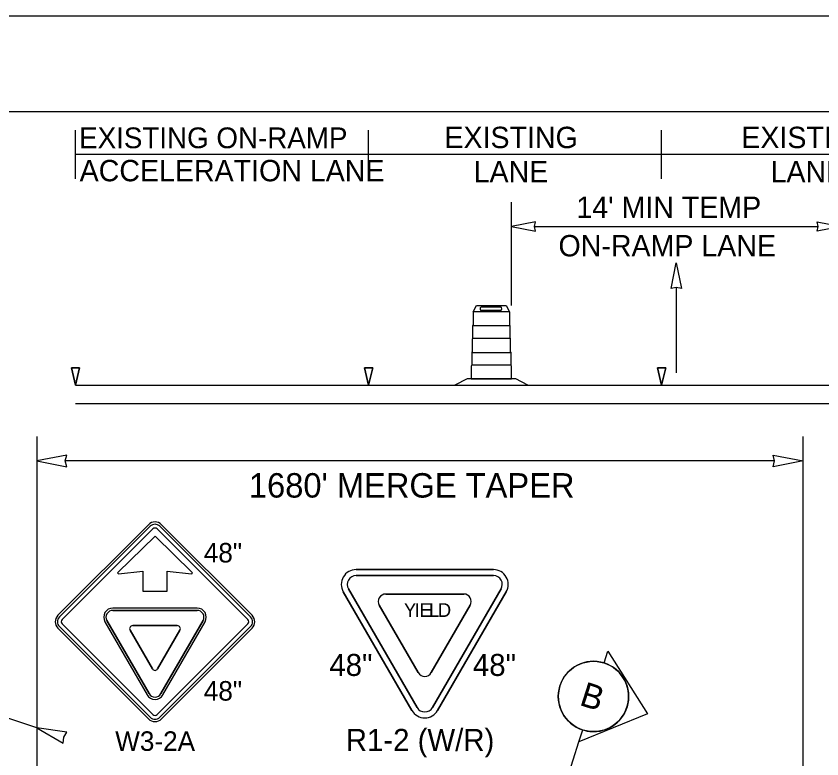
# Model space of a CAD drawing. Extents: x 99999 to 100116, y 99995 to 100013.
# Drawn here: x 100090.535 to 100093.175, y 100008.254 to 100010.687 of the extents above; entities that cross this region are included whole.
import ezdxf

# ---------------------------------------------------------------- set-up
doc = ezdxf.new("R2010")
doc.units = 0
for name, color, linetype in [('Default', 7, 'Continuous'), ('SH_GI_PlotLimits', 7, 'Continuous'), ('SH_GI_SectionCut', 7, 'Continuous'), ('SH_GI_SheetBorder', 7, 'Continuous'), ('TR_SN_ConstructionSigns', 7, 'Continuous'), ('TR_WZ_ArrowLeftStrRightTurn', 7, 'Continuous'), ('TR_WZ_TrafficSafetyDrumElev', 7, 'Continuous'), ('TR_WZ_WorkZoneDetails', 7, 'Continuous'), ('TR_WZ_WorkZoneTextCurrent', 7, 'Continuous')]:
    doc.layers.add(name, color=color, linetype=linetype)

msp = doc.modelspace()

# ---------------------------------------------------------------- linework, layer by layer
at = {"layer": 'Default'}
for p, q in [((100090.9689, 100009.0212), (100090.6719, 100008.7242)), ((100091.3083, 100008.7242), (100091.0113, 100009.0212)), ((100090.6719, 100008.6818), (100090.9689, 100008.3848)), ((100091.0113, 100008.3848), (100091.3083, 100008.6818))]:
    msp.add_line(p, q, dxfattribs=at)
for centre, start, end in [((100090.9901, 100009), 45, 135), ((100090.6931, 100008.703), 135, 225), ((100091.2871, 100008.703), 315, 45), ((100090.9901, 100008.406), 225, 315)]:
    msp.add_arc(centre, 0.03, start, end, dxfattribs=at)
at = {"layer": 'SH_GI_PlotLimits'}
msp.add_lwpolyline([(100079.0625, 99999.6875), (100096.0625, 99999.6875), (100096.0625, 100010.6875), (100079.0625, 100010.6875)], close=True, dxfattribs=at)
at = {"layer": 'SH_GI_SectionCut'}
for p, q in [((100092.4616, 100008.5681), (100092.474, 100008.6069)), ((100092.474, 100008.6069), (100092.6038, 100008.4017)), ((100092.6038, 100008.4017), (100092.3791, 100008.3098)), ((100092.3791, 100008.3098), (100092.3915, 100008.3486)), ((100092.1583, 100007.619), (100092.3791, 100008.3098))]:
    msp.add_line(p, q, dxfattribs=at)
msp.add_circle((100092.4266, 100008.4583), 0.1152, dxfattribs=at)
for start, end in [(72.2795, 342.2772), (252.275, 72.2795), (342.2772, 72.2795)]:
    msp.add_arc((100092.4266, 100008.4583), 0.1152, start, end, dxfattribs=at)
at = {"layer": 'SH_GI_SheetBorder'}
msp.add_line((100080, 100010.375), (100095.75, 100010.375), dxfattribs=at)
at = {"layer": 'TR_SN_ConstructionSigns'}
for p, q in [((100090.6719, 100008.7242), (100090.9689, 100009.0212)), ((100090.9742, 100009.0159), (100090.6772, 100008.7189)), ((100090.686, 100008.7101), (100090.983, 100009.0071)), ((100090.9971, 100009.0071), (100091.2941, 100008.7101)), ((100091.303, 100008.7189), (100091.006, 100009.0159)), ((100091.0113, 100009.0212), (100091.3083, 100008.7242)), ((100090.9901, 100008.983), (100090.8683, 100008.8648)), ((100091.1118, 100008.8648), (100090.9901, 100008.983)), ((100090.8703, 100008.8605), (100090.9501, 100008.8688)), ((100090.9501, 100008.8688), (100090.9501, 100008.803)), ((100091.0301, 100008.803), (100091.0301, 100008.8688)), ((100091.0301, 100008.8688), (100091.1098, 100008.8605)), ((100092.0987, 100008.874), (100091.6491, 100008.874)), ((100091.6491, 100008.8545), (100091.6491, 100008.8547)), ((100091.6491, 100008.8547), (100091.8739, 100008.8547)), ((100091.8739, 100008.8547), (100091.6491, 100008.8547)), ((100091.6491, 100008.8547), (100091.6491, 100008.8545)), ((100090.9501, 100008.803), (100091.0301, 100008.803)), ((100091.8317, 100008.4123), (100091.6069, 100008.8009)), ((100091.6069, 100008.8009), (100091.8317, 100008.4123)), ((100091.8486, 100008.4221), (100091.6238, 100008.8107)), ((100091.6238, 100008.8107), (100091.8486, 100008.4221)), ((100091.8739, 100008.7938), (100091.7461, 100008.7938)), ((100091.7461, 100008.7938), (100091.8739, 100008.7938)), ((100092.0017, 100008.7938), (100091.8739, 100008.7938)), ((100091.8739, 100008.7938), (100092.0017, 100008.7938)), ((100092.124, 100008.8107), (100091.8992, 100008.4221)), ((100091.8992, 100008.4221), (100092.124, 100008.8107)), ((100092.1408, 100008.8009), (100091.916, 100008.4123)), ((100091.916, 100008.4123), (100092.1408, 100008.8009)), ((100091.1281, 100008.748), (100090.852, 100008.748)), ((100090.852, 100008.7405), (100091.1281, 100008.7405)), ((100091.1281, 100008.7405), (100090.852, 100008.7405)), ((100091.725, 100008.7573), (100091.8528, 100008.5364)), ((100091.8528, 100008.5364), (100091.725, 100008.7573)), ((100091.895, 100008.5364), (100092.0228, 100008.7573)), ((100092.0228, 100008.7573), (100091.895, 100008.5364)), ((100090.9689, 100008.3848), (100090.6719, 100008.6818)), ((100090.6772, 100008.6871), (100090.9742, 100008.3901)), ((100090.983, 100008.399), (100090.686, 100008.6959)), ((100090.8261, 100008.703), (100090.9641, 100008.4639)), ((100090.9706, 100008.4677), (100090.8326, 100008.7068)), ((100090.8326, 100008.7068), (100090.9706, 100008.4677)), ((100091.0632, 100008.6905), (100090.917, 100008.6905)), ((100090.917, 100008.6905), (100091.0632, 100008.6905)), ((100091.2941, 100008.6959), (100090.9971, 100008.399)), ((100091.006, 100008.3901), (100091.303, 100008.6871)), ((100091.1476, 100008.7068), (100091.0096, 100008.4677)), ((100091.0096, 100008.4677), (100091.1476, 100008.7068)), ((100091.3083, 100008.6818), (100091.0113, 100008.3848)), ((100091.0161, 100008.4639), (100091.1541, 100008.703)), ((100090.9083, 100008.6755), (100090.9814, 100008.5489)), ((100090.9814, 100008.5489), (100090.9083, 100008.6755)), ((100090.9987, 100008.5489), (100091.0718, 100008.6755)), ((100091.0718, 100008.6755), (100090.9987, 100008.5489))]:
    msp.add_line(p, q, dxfattribs=at)
for points in [[(100091.6491, 100008.874), (100092.0987, 100008.874)], [(100091.8739, 100008.8547), (100092.0987, 100008.8547), (100092.0987, 100008.8545)], [(100092.0987, 100008.8545), (100092.0987, 100008.8547), (100091.8739, 100008.8547)]]:
    msp.add_lwpolyline(points, dxfattribs=at)
for centre, radius, start, end in [((100090.9901, 100009), 0.03, 45, 135), ((100090.9901, 100009), 0.0225, 45, 135), ((100090.9901, 100009), 0.01, 45, 135), ((100091.6491, 100008.8253), 0.0487, 90, 210.0517), ((100091.6491, 100008.8253), 0.0487, 90, 210.0517), ((100092.0987, 100008.8253), 0.0487, 329.9522, 90), ((100092.0987, 100008.8253), 0.0487, 329.9522, 90), ((100090.8701, 100008.863), 0.0025, 134.1559, 275.9533), ((100091.1101, 100008.863), 0.0025, 264.0467, 45.8441), ((100091.6491, 100008.8253), 0.0292, 90, 210.0517), ((100091.6491, 100008.8253), 0.0292, 90, 210.0517), ((100092.0987, 100008.8253), 0.0292, 329.9522, 90), ((100092.0987, 100008.8253), 0.0292, 329.9522, 90), ((100091.7461, 100008.7695), 0.0244, 90, 210.0513), ((100091.7461, 100008.7695), 0.0244, 90, 210.0513), ((100092.0017, 100008.7695), 0.0244, 329.9514, 90), ((100092.0017, 100008.7695), 0.0244, 329.9514, 90), ((100090.852, 100008.718), 0.03, 90, 210), ((100090.852, 100008.718), 0.0225, 90, 210), ((100090.852, 100008.718), 0.0225, 90, 210), ((100091.1281, 100008.718), 0.03, 330, 90), ((100091.1281, 100008.718), 0.0225, 330, 90), ((100091.1281, 100008.718), 0.0225, 330, 90), ((100090.6931, 100008.703), 0.03, 135, 225), ((100090.6931, 100008.703), 0.0225, 135, 225), ((100090.6931, 100008.703), 0.01, 135, 225), ((100091.2871, 100008.703), 0.01, 315, 45), ((100091.2871, 100008.703), 0.0225, 315, 45), ((100091.2871, 100008.703), 0.03, 315, 45), ((100090.917, 100008.6805), 0.01, 90, 210), ((100090.917, 100008.6805), 0.01, 90, 210), ((100091.0632, 100008.6805), 0.01, 330, 90), ((100091.0632, 100008.6805), 0.01, 330, 90), ((100090.9901, 100008.5539), 0.01, 210, 330), ((100090.9901, 100008.5539), 0.01, 210, 330), ((100091.8739, 100008.5486), 0.0244, 210.0519, 329.9525), ((100091.8739, 100008.5486), 0.0244, 210.0519, 329.9525), ((100090.9901, 100008.4789), 0.03, 210, 330), ((100090.9901, 100008.4789), 0.0225, 210, 330), ((100090.9901, 100008.4789), 0.0225, 210, 330), ((100091.8739, 100008.4367), 0.0292, 210.0518, 329.9516), ((100091.8739, 100008.4367), 0.0292, 210.0518, 329.9516), ((100090.9901, 100008.406), 0.01, 225, 315), ((100091.8739, 100008.4367), 0.0487, 210.0518, 329.9516), ((100091.8739, 100008.4367), 0.0487, 210.0518, 329.9516), ((100090.9901, 100008.406), 0.03, 225, 315), ((100090.9901, 100008.406), 0.0225, 225, 315)]:
    msp.add_arc(centre, radius, start, end, dxfattribs=at)
at = {"layer": 'TR_WZ_ArrowLeftStrRightTurn'}
msp.add_line((100092.698, 100009.7986), (100092.698, 100009.5187), dxfattribs=at)
msp.add_lwpolyline([(100092.698, 100009.8787), (100092.7145, 100009.7947), (100092.698, 100009.7986), (100092.6815, 100009.7947)], close=True, dxfattribs=at)
at = {"layer": 'TR_WZ_TrafficSafetyDrumElev'}
for p, q in [((100092.1513, 100009.7188), (100092.0329, 100009.7188)), ((100092.1513, 100009.7188), (100092.0329, 100009.7188)), ((100092.1237, 100009.734), (100092.0583, 100009.734)), ((100092.0583, 100009.7236), (100092.1237, 100009.7236)), ((100092.1536, 100009.6724), (100092.0306, 100009.6724)), ((100092.0306, 100009.6724), (100092.0306, 100009.6325)), ((100092.1536, 100009.6325), (100092.1536, 100009.6724)), ((100092.0306, 100009.6325), (100092.1536, 100009.6325)), ((100092.1565, 100009.5844), (100092.0277, 100009.5844)), ((100092.0277, 100009.5844), (100092.0277, 100009.5445)), ((100092.1565, 100009.5445), (100092.1565, 100009.5844)), ((100092.0277, 100009.5445), (100092.1565, 100009.5445))]:
    msp.add_line(p, q, dxfattribs=at)
for points in [[(100092.0329, 100009.7188), (100092.0434, 100009.7388), (100092.1408, 100009.7388), (100092.1513, 100009.7188)], [(100092.2121, 100009.4788), (100092.1719, 100009.4988), (100092.0123, 100009.4988), (100091.9721, 100009.4788)]]:
    msp.add_lwpolyline(points, close=True, dxfattribs=at)
for points in [[(100092.0321, 100009.7172), (100092.0321, 100009.676)], [(100092.0321, 100009.7172), (100092.0321, 100009.676)], [(100092.1521, 100009.676), (100092.1521, 100009.7172)], [(100092.1521, 100009.676), (100092.1521, 100009.7172)], [(100092.0306, 100009.673), (100092.0306, 100009.632)], [(100092.0306, 100009.673), (100092.0306, 100009.632)], [(100092.1536, 100009.632), (100092.1536, 100009.673)], [(100092.1536, 100009.632), (100092.1536, 100009.673)], [(100092.0291, 100009.629), (100092.0291, 100009.5879)], [(100092.0291, 100009.629), (100092.0291, 100009.5879)], [(100092.155, 100009.5879), (100092.155, 100009.629)], [(100092.155, 100009.5879), (100092.155, 100009.629)], [(100092.0277, 100009.5849), (100092.0277, 100009.5439)], [(100092.0277, 100009.5849), (100092.0277, 100009.5439)], [(100092.1565, 100009.5439), (100092.1565, 100009.5849)], [(100092.1565, 100009.5439), (100092.1565, 100009.5849)], [(100092.0262, 100009.5409), (100092.0262, 100009.4988), (100092.158, 100009.4988), (100092.158, 100009.5409)], [(100092.0262, 100009.5409), (100092.0262, 100009.4988), (100092.158, 100009.4988), (100092.158, 100009.5409)]]:
    msp.add_lwpolyline(points, dxfattribs=at)
for centre, major_axis, ratio, start_param, end_param in [((100092.0331, 100009.7168), (0, 0.00199), 0.493438, 0.177149, 1.393647), ((100092.0331, 100009.7168), (0, 0.00199), 0.493438, 0.177149, 1.393647), ((100092.0583, 100009.7288), (0, 0.0052), 0.570305, 6.283185, 9.424778), ((100092.1237, 100009.7288), (0, 0.0052), 0.570305, 3.141593, 6.283185), ((100092.1511, 100009.7168), (0, 0.00199), 0.493438, 4.889538, 6.106036), ((100092.1511, 100009.7168), (0, 0.00199), 0.493438, 4.889538, 6.106036), ((100092.0333, 100009.6705), (0, 0.00606), 0.493438, 0.4288, 1.141997), ((100092.0333, 100009.6705), (0, 0.00606), 0.493438, 0.4288, 1.141997), ((100092.1508, 100009.6705), (0, 0.00606), 0.493438, 5.141189, 5.854386), ((100092.1508, 100009.6705), (0, 0.00606), 0.493438, 5.141189, 5.854386), ((100092.0319, 100009.6265), (0, 0.00606), 0.493438, 0.4288, 1.141997), ((100092.0319, 100009.6265), (0, 0.00606), 0.493438, 0.4288, 1.141997), ((100092.1523, 100009.6265), (0, 0.00606), 0.493438, 5.141189, 5.854386), ((100092.1523, 100009.6265), (0, 0.00606), 0.493438, 5.141189, 5.854386), ((100092.0304, 100009.5824), (0, 0.00606), 0.493438, 0.4288, 1.141997), ((100092.0304, 100009.5824), (0, 0.00606), 0.493438, 0.4288, 1.141997), ((100092.1538, 100009.5824), (0, 0.00606), 0.493438, 5.141189, 5.854386), ((100092.1538, 100009.5824), (0, 0.00606), 0.493438, 5.141189, 5.854386), ((100092.0289, 100009.5384), (0, 0.00606), 0.493438, 0.4288, 1.141997), ((100092.0289, 100009.5384), (0, 0.00606), 0.493438, 0.4288, 1.141997), ((100092.1553, 100009.5384), (0, 0.00606), 0.493438, 5.141189, 5.854386), ((100092.1553, 100009.5384), (0, 0.00606), 0.493438, 5.141189, 5.854386)]:
    msp.add_ellipse(centre, major_axis=major_axis, ratio=ratio, start_param=start_param, end_param=end_param, dxfattribs=at)
at = {"layer": 'TR_WZ_WorkZoneDetails'}
for p, q in [((100090.7298, 100010.154), (100090.7298, 100010.314)), ((100091.6898, 100010.154), (100091.6898, 100010.314)), ((100092.6498, 100010.154), (100092.6498, 100010.314)), ((100091.6898, 100010.234), (100090.7298, 100010.234)), ((100092.6498, 100010.234), (100091.6898, 100010.234)), ((100093.6098, 100010.234), (100092.6498, 100010.234)), ((100092.158, 100009.7388), (100092.158, 100010.0783)), ((100092.233, 100009.9983), (100093.163, 100009.9983)), ((100090.7298, 100009.4787), (100094.4098, 100009.4787)), ((100090.7298, 100009.4187), (100094.4098, 100009.4187)), ((100090.6024, 100009.31), (100090.6024, 100005.4763)), ((100093.1135, 100007.1854), (100093.1135, 100009.31)), ((100093.0198, 100009.23), (100090.6962, 100009.23)), ((100090.6024, 100008.355), (100090.2815, 100008.4612))]:
    msp.add_line(p, q, dxfattribs=at)
for points in [[(100092.158, 100009.9983), (100092.2366, 100009.9829), (100092.233, 100009.9983), (100092.2366, 100010.0137)], [(100093.238, 100009.9983), (100093.1594, 100009.9829), (100093.163, 100009.9983), (100093.1594, 100010.0137)], [(100090.7298, 100009.4787), (100090.7432, 100009.5346), (100090.7165, 100009.5346)], [(100091.6898, 100009.4787), (100091.7032, 100009.5346), (100091.6765, 100009.5346)], [(100092.6498, 100009.4787), (100092.6632, 100009.5346), (100092.6365, 100009.5346)], [(100090.6024, 100009.23), (100090.7007, 100009.2107), (100090.6962, 100009.23), (100090.7007, 100009.2493)], [(100093.1135, 100009.23), (100093.0152, 100009.2107), (100093.0198, 100009.23), (100093.0152, 100009.2493)], [(100090.6024, 100008.355), (100090.6893, 100008.3051), (100090.6912, 100008.3249), (100090.7017, 100008.3416)]]:
    msp.add_lwpolyline(points, close=True, dxfattribs=at)
for points in [[(100090.7165, 100009.5346), (100090.7432, 100009.5346), (100090.7298, 100009.4787), (100090.7165, 100009.5346)], [(100091.6765, 100009.5346), (100091.7032, 100009.5346), (100091.6898, 100009.4787), (100091.6765, 100009.5346)], [(100092.6365, 100009.5346), (100092.6632, 100009.5346), (100092.6498, 100009.4787), (100092.6365, 100009.5346)]]:
    msp.add_lwpolyline(points, dxfattribs=at)

# ---------------------------------------------------------------- texts
at = {"layer": 'Default'}
for s, p in [('Y', (100091.8057, 100008.7189)), ('I', (100091.8408, 100008.7189)), ('E', (100091.857, 100008.7189)), ('L', (100091.8876, 100008.7189)), ('D', (100091.9168, 100008.7189))]:
    msp.add_text(s, height=0.045, dxfattribs=at).set_placement(p)
at = {"layer": 'SH_GI_SectionCut'}
msp.add_text('B', height=0.08, rotation=342.2872, dxfattribs=at).set_placement((100092.3773, 100008.4313))
at = {"layer": 'TR_SN_ConstructionSigns'}
for s, height, p in [('48"', 0.064, (100091.1499, 100008.8973)), ('48"', 0.072, (100091.5613, 100008.5256)), ('48"', 0.072, (100092.0316, 100008.5256)), ('48"', 0.064, (100091.1499, 100008.4447)), ('W3-2A', 0.064, (100090.8597, 100008.28)), ('R1-2 (W/R)', 0.072, (100091.6151, 100008.28))]:
    msp.add_text(s, height=height, dxfattribs=at).set_placement(p)
at = {"layer": 'TR_WZ_WorkZoneDetails'}
for s, height, p in [('EXISTING ON-RAMP', 0.068, (100090.7415, 100010.2547)), ('EXISTING', 0.07, (100091.9383, 100010.255)), ('EXISTING', 0.07, (100092.911, 100010.255)), ('ACCELERATION LANE', 0.07, (100090.7432, 100010.1463)), ('LANE', 0.07, (100092.034, 100010.143)), ('LANE', 0.07, (100093.0068, 100010.143)), ("14' MIN TEMP", 0.07, (100092.3705, 100010.0263)), ('ON-RAMP LANE', 0.07, (100092.312, 100009.9003))]:
    msp.add_text(s, height=height, dxfattribs=at).set_placement(p)
at = {"layer": 'TR_WZ_WorkZoneTextCurrent'}
msp.add_text("1680' MERGE TAPER", height=0.08, dxfattribs=at).set_placement((100091.2977, 100009.11))

doc.saveas('drawing.dxf')
